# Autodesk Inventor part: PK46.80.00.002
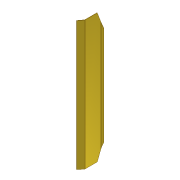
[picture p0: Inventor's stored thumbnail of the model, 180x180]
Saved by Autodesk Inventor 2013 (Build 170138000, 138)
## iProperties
Shininess: 64.0
Length Units: 11269
Angle Units: 11279
Time Units: 11290
Mass Units: 11283
Length Display Precision: 3
Angle Display Precision: 2
Compacted: True
Part Number: PK46.80.00.002
Document SubType Name: Sheet Metal
Created: 2004-12
Material: Steel, Mild
Designer: Salex
Manufacturer: Standard
Standards Organization: Custom
Density: 7.86 g/cm^3
Sheet Metal Rule: Default
Mass: 75176.4 g
Surface Area: 24385.2 cm^2
Volume: 9564.43 cm^3
Density: 0.0
Volumn: 0.0
Area: 0.0
PropertySet Name: Model Information
Control State: 0
Master: False
Checked Out: False
Checked Out Date: 2008-10-15
Last Check In Date: 2008-10-15
Author: Salex
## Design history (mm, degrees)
node "Contour Flange1"
  sketch "Sketch1"
    geometry: L1 (0, 0)-(0, 360); L2 (0, 0)-(-70, -90)
    constraints: 4 end point, 1 vertical, 1 other
    dimensions: "d16" = 70 horizontal distance of L1.start L2.end; "d19" = 360 distance of L1.start L1.end; "d23" = 90 vertical distance of L1.start L2.end
feature "Угловая фаска3" dims "d25" = 300, "d26" = 115, angle "d27" = 45 deg
feature "Угловая фаска4" dims "d28" = 300 (= d25), "d29" = 115 (= d26), angle "d30" = 45 deg
node "РабОсь1"
feature "Сгиб по линии1" dims "d32" = 8 (= BendReliefWidth), "d33" = 4 (= BendReliefDepth), "d34" = 16 (= MinimumRemnant), "d35" = 10 (= BendRadius), "d36" = 50 deg, "d37" = 10 (= BendRadius), "SeamGap" = 0.01, "Thickness" = 8
node "РабПлоскость1"
node "РабПлоскость2"
body "Solid1"
sketch "Эскиз3"
  geometry: L1 (2280, 356.569)-(2580, 241.569) reference; L2 (2280, 356.569)-(300, 356.569) reference; L3 (0, 241.569)-(300, 356.569) reference; L4 (195.652, 316.569)-(2384.348, 316.569)
  constraints: 2 end point, 2 point on line, 1 parallel
  dimensions: "d31" = 40 distance between parallel lines of L2 L4
face "Plate1" dims "d3" = 2580, "d4" = 8 (= BendReliefWidth), "d6" = 16 (= MinimumRemnant), "d8" = 10 (= BendRadius), "d9" = 8, "Thickness" = 8
bend "Bend1" dims "d4" = 8 (= BendReliefWidth), "d5" = 4 (= BendReliefDepth), "d6" = 16 (= MinimumRemnant), "d7" = 10 (= BendRadius), "d8" = 10 (= BendRadius), "d9" = 8, "SeamGap" = 0.01, "Thickness" = 8
other parameters: "BendRadius" = 10, "BendReliefWidth" = 8 (= Thickness), "BendReliefDepth" = 4 (= 0.5 x Thickness), "CornerReliefSize" = 32 (= 4 x Thickness), "MinimumRemnant" = 16 (= 2 x Thickness), "d38" = 90 deg, "d39" = 0, "JacobiRadiusSize" = 8 (= Thickness), "GapSize" = 8 (= Thickness)
